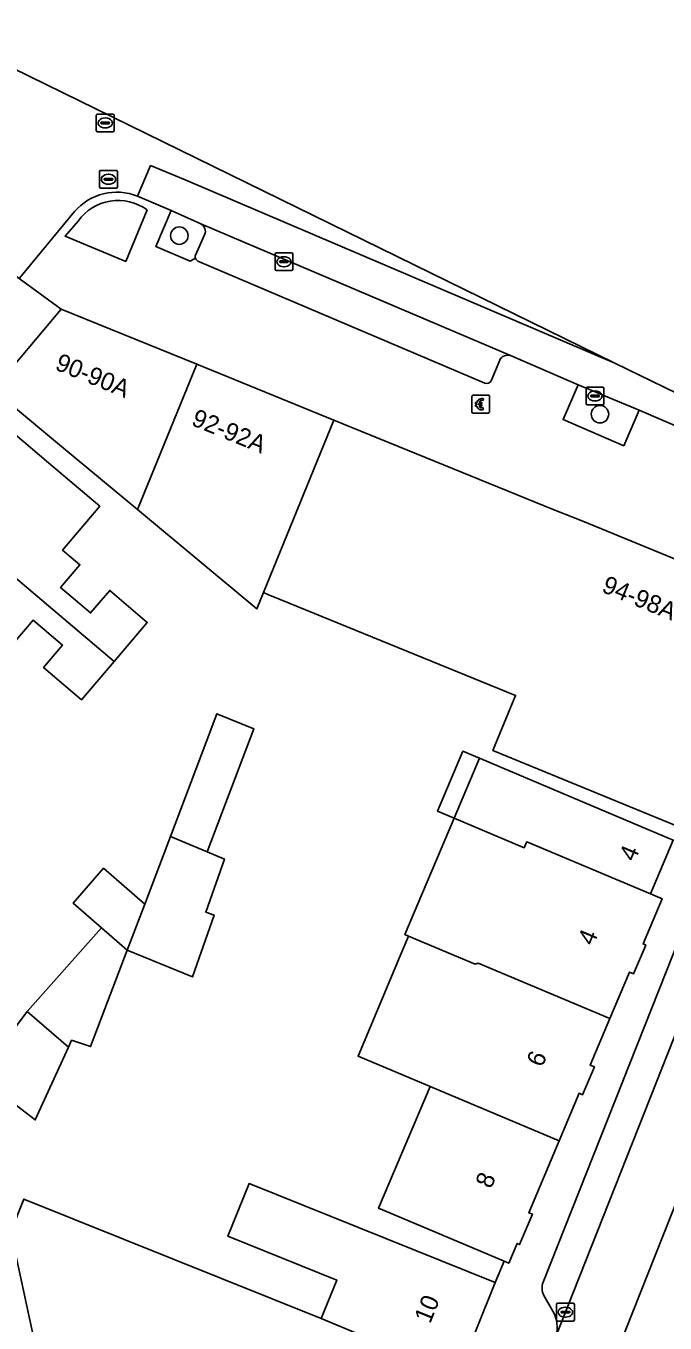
# Model space of a CAD drawing. Extents: x 161798 to 162385, y 382315 to 382833.
# Drawn here: x 162153.3 to 162189.2, y 382587 to 382659.8 of the extents above; entities that cross this region are included whole.
import ezdxf

# ---------------------------------------------------------------- set-up
doc = ezdxf.new("R2010")
doc.units = 0
for name, color, linetype in [('IMGEO_Betaalautomaat', 7, 'Continuous'), ('IMGEO_Boom', 7, 'Continuous'), ('IMGEO_Erf', 7, 'Continuous'), ('IMGEO_Groenvoorziening', 7, 'Continuous'), ('IMGEO_Kolk', 7, 'Continuous'), ('IMGEO_Pand', 7, 'Continuous'), ('IMGEO_Pand_nummerreeks', 7, 'Continuous'), ('IMGEO_Parkeervlak_open', 7, 'Continuous'), ('IMGEO_Rijbaan_lokaal_gesloten', 7, 'Continuous'), ('IMGEO_Rijbaan_lokaal_open', 7, 'Continuous'), ('IMGEO_Rioolput', 7, 'Continuous'), ('IMGEO_Voetpad_open', 7, 'Continuous')]:
    doc.layers.add(name, color=color, linetype=linetype)

msp = doc.modelspace()

# ---------------------------------------------------------------- linework, layer by layer
at = {"layer": 'IMGEO_Betaalautomaat'}
for p, q in [((162178.31, 382638.121), (162178.31, 382638.962)), ((162178.31, 382638.962), (162178.31, 382638.121)), ((162178.385, 382639.045), (162179.226, 382639.045)), ((162179.226, 382639.045), (162178.385, 382639.045)), ((162179.309, 382638.971), (162179.309, 382638.13)), ((162179.309, 382638.13), (162179.309, 382638.971)), ((162178.593, 382638.509), (162178.593, 382638.577)), ((162178.714, 382638.577), (162178.714, 382638.509)), ((162178.972, 382638.85), (162178.955, 382638.75)), ((162178.959, 382638.344), (162178.981, 382638.257)), ((162179.235, 382638.046), (162178.394, 382638.046)), ((162178.394, 382638.046), (162179.235, 382638.046))]:
    msp.add_line(p, q, dxfattribs=at)
for points in [[(162178.593, 382638.577), (162178.524, 382638.577), (162178.524, 382638.646), (162178.603, 382638.646)], [(162178.598, 382638.44), (162178.524, 382638.44), (162178.524, 382638.509), (162178.593, 382638.509)], [(162178.725, 382638.646), (162178.872, 382638.646), (162178.872, 382638.577), (162178.714, 382638.577)], [(162178.714, 382638.509), (162178.872, 382638.509), (162178.872, 382638.44), (162178.728, 382638.44)]]:
    msp.add_lwpolyline(points, dxfattribs=at)
for centre, radius, start, end in [((162178.388, 382638.968), 0.0779, 92.4484, 184.28452), ((162178.388, 382638.968), 0.0779, 92.4484, 184.28452), ((162179.232, 382638.968), 0.0779, 2.4484, 94.28452), ((162179.232, 382638.968), 0.0779, 2.4484, 94.28452), ((162178.859, 382638.495), 0.267, 191.80956, 297.03891), ((162178.886, 382638.57), 0.293, 73.01398, 165.01395), ((162178.892, 382638.583), 0.179, 69.32359, 159.56827), ((162178.892, 382638.51), 0.179, 202.76249, 291.86925), ((162178.388, 382638.124), 0.0779, 182.4484, 274.28452), ((162178.388, 382638.124), 0.0779, 182.4484, 274.28452), ((162179.232, 382638.124), 0.0779, 272.4484, 4.28452), ((162179.232, 382638.124), 0.0779, 272.4484, 4.28452)]:
    msp.add_arc(centre, radius, start, end, dxfattribs=at)
at = {"layer": 'IMGEO_Boom'}
for centre in [(162161.894, 382648.007), (162185.512, 382637.983)]:
    msp.add_circle(centre, 0.489, dxfattribs=at)
at = {"layer": 'IMGEO_Erf'}
for points in [[(162189.718, 382614.907), (162179.5, 382619.11), (162180.771, 382622.2), (162167.559, 382627.583), (162166.862, 382627.867), (162166.619, 382627.966), (162166.249, 382627.058), (162159.547, 382632.625), (162155.283, 382636.167), (162151.434, 382639.358)], [(162150.752, 382638.476), (162154.546, 382635.258), (162157.427, 382632.815), (162155.342, 382630.356), (162156.314, 382629.532), (162155.23, 382628.253), (162156.914, 382626.824), (162157.985, 382628.086), (162160.094, 382626.297), (162158.226, 382624.094), (162156.409, 382621.952), (162154.269, 382623.768), (162155.33, 382625.019), (162153.684, 382626.414), (162152.605, 382625.142)], [(162153.719, 382586.097), (162152.432, 382592.088), (162153.17, 382593.924), (162169.858, 382587.213), (162170.728, 382589.376), (162164.617, 382591.834), (162165.808, 382594.796), (162179.636, 382589.236), (162180.133, 382590.434), (162175.788, 382592.269), (162173.084, 382593.41), (162175.969, 382600.244), (162171.926, 382601.949), (162174.296, 382607.57), (162174.764, 382608.68), (162174.561, 382608.766), (162177.32, 382615.302), (162176.391, 382615.693), (162177.812, 382619.058), (162178.74, 382618.666), (162185.017, 382616.016), (162189.623, 382614.072)]]:
    msp.add_lwpolyline(points, dxfattribs=at)
msp.add_lwpolyline([(162153.357, 382604.46), (162157.522, 382609.158), (162155.937, 382610.533), (162157.637, 382612.493), (162159.954, 382610.482), (162161.391, 382614.281), (162163.398, 382619.568), (162164.006, 382621.171), (162166.079, 382620.322), (162163.458, 382613.415), (162164.421, 382613.012), (162163.386, 382610.027), (162163.843, 382609.869), (162162.639, 382606.397), (162158.97, 382607.901), (162156.913, 382602.479), (162155.839, 382602.843), (162155.664, 382602.458), (162153.802, 382598.368), (162150.609, 382600.809)], close=True, dxfattribs=at)
at = {"layer": 'IMGEO_Groenvoorziening'}
for points in [[(162156.208, 382648.82), (162155.475, 382647.977), (162158.88, 382646.556), (162160.087, 382649.446)], [(162163.099, 382648.663), (162161.431, 382649.415), (162160.58, 382647.389), (162162.505, 382646.576), (162162.801, 382646.737)], [(162162.794, 382646.916), (162163.309, 382648.058)]]:
    msp.add_lwpolyline(points, dxfattribs=at)
msp.add_lwpolyline([(162187.705, 382638.215), (162184.295, 382639.63), (162183.445, 382637.678), (162186.844, 382636.214)], close=True, dxfattribs=at)
for centre, radius, start, end in [((162158.455, 382647.225), 2.756, 53.70431, 144.6306), ((162162.905, 382648.257), 0.45, 333.83939, 64.44515), ((162163.087, 382646.838), 0.304, 165.08541, 199.39355)]:
    msp.add_arc(centre, radius, start, end, dxfattribs=at)
at = {"layer": 'IMGEO_Kolk'}
for p, q in [((162167.266, 382646.117), (162167.266, 382646.969)), ((162167.341, 382647.043), (162168.193, 382647.043)), ((162168.267, 382646.969), (162168.267, 382646.117)), ((162167.525, 382646.537), (162167.525, 382646.549)), ((162167.963, 382646.5), (162167.565, 382646.5)), ((162167.568, 382646.586), (162167.966, 382646.586)), ((162167.777, 382646.263), (162167.752, 382646.263)), ((162167.754, 382646.823), (162167.779, 382646.823)), ((162168.009, 382646.549), (162168.009, 382646.537)), ((162168.193, 382646.043), (162167.341, 382646.043)), ((162184.734, 382638.579), (162184.734, 382639.431)), ((162184.809, 382639.505), (162185.661, 382639.505)), ((162184.993, 382638.999), (162184.993, 382639.011)), ((162185.431, 382638.962), (162185.033, 382638.962)), ((162185.036, 382639.048), (162185.434, 382639.048)), ((162185.222, 382639.285), (162185.247, 382639.285)), ((162185.477, 382639.011), (162185.477, 382638.999)), ((162185.735, 382639.431), (162185.735, 382638.579)), ((162185.661, 382638.505), (162184.809, 382638.505)), ((162185.245, 382638.725), (162185.22, 382638.725)), ((162183.072, 382587.148), (162183.072, 382588)), ((162183.147, 382588.074), (162183.999, 382588.074)), ((162184.073, 382588), (162184.073, 382587.148)), ((162183.331, 382587.568), (162183.331, 382587.58)), ((162183.769, 382587.531), (162183.371, 382587.531)), ((162183.374, 382587.617), (162183.772, 382587.617)), ((162183.583, 382587.294), (162183.558, 382587.294)), ((162183.56, 382587.854), (162183.585, 382587.854)), ((162183.815, 382587.58), (162183.815, 382587.568)), ((162183.999, 382587.074), (162183.147, 382587.074))]:
    msp.add_line(p, q, dxfattribs=at)
for points in [[(162167.266, 382646.117), (162167.266, 382646.969)], [(162167.341, 382647.043), (162168.193, 382647.043)], [(162168.267, 382646.969), (162168.267, 382646.117)], [(162168.193, 382646.043), (162167.341, 382646.043)], [(162184.734, 382638.579), (162184.734, 382639.431)], [(162184.809, 382639.505), (162185.661, 382639.505)], [(162185.735, 382639.431), (162185.735, 382638.579)], [(162185.661, 382638.505), (162184.809, 382638.505)], [(162183.072, 382587.148), (162183.072, 382588)], [(162183.147, 382588.074), (162183.999, 382588.074)], [(162184.073, 382588), (162184.073, 382587.148)], [(162183.999, 382587.074), (162183.147, 382587.074)]]:
    msp.add_lwpolyline(points, dxfattribs=at)
for centre, radius, start, end in [((162167.343, 382646.967), 0.0765, 91.55205, 178.44795), ((162167.343, 382646.967), 0.0765, 91.55205, 178.44795), ((162168.191, 382646.967), 0.0765, 1.55205, 88.44795), ((162168.191, 382646.967), 0.0765, 1.55205, 88.44795), ((162167.565, 382646.546), 0.0403, 85.87752, 175.75265), ((162167.562, 382646.536), 0.0366, 178.93798, 274.71019), ((162167.966, 382646.543), 0.043, 264.86636, 352.45326), ((162167.97, 382646.548), 0.0386, 1.73085, 96.63898), ((162167.343, 382646.119), 0.0765, 181.55205, 268.44795), ((162167.343, 382646.119), 0.0765, 181.55205, 268.44795), ((162168.191, 382646.119), 0.0765, 271.55205, 358.44795), ((162168.191, 382646.119), 0.0765, 271.55205, 358.44795), ((162184.811, 382639.429), 0.0765, 91.55205, 178.44795), ((162184.811, 382639.429), 0.0765, 91.55205, 178.44795), ((162185.033, 382639.008), 0.0403, 85.87752, 175.75265), ((162185.03, 382638.998), 0.0366, 178.93798, 274.71019), ((162185.434, 382639.005), 0.043, 264.86636, 352.45326), ((162185.438, 382639.01), 0.0386, 1.73085, 96.63898), ((162185.659, 382639.429), 0.0765, 1.55205, 88.44795), ((162185.659, 382639.429), 0.0765, 1.55205, 88.44795), ((162184.811, 382638.581), 0.0765, 181.55205, 268.44795), ((162184.811, 382638.581), 0.0765, 181.55205, 268.44795), ((162185.659, 382638.581), 0.0765, 271.55205, 358.44795), ((162185.659, 382638.581), 0.0765, 271.55205, 358.44795), ((162183.149, 382587.998), 0.0765, 91.55205, 178.44795), ((162183.149, 382587.998), 0.0765, 91.55205, 178.44795), ((162183.997, 382587.998), 0.0765, 1.55205, 88.44795), ((162183.997, 382587.998), 0.0765, 1.55205, 88.44795), ((162183.371, 382587.577), 0.0403, 85.87752, 175.75265), ((162183.368, 382587.567), 0.0366, 178.93798, 274.71019), ((162183.772, 382587.574), 0.043, 264.86636, 352.45326), ((162183.776, 382587.579), 0.0386, 1.73085, 96.63898), ((162183.149, 382587.15), 0.0765, 181.55205, 268.44795), ((162183.149, 382587.15), 0.0765, 181.55205, 268.44795), ((162183.997, 382587.15), 0.0765, 271.55205, 358.44795), ((162183.997, 382587.15), 0.0765, 271.55205, 358.44795)]:
    msp.add_arc(centre, radius, start, end, dxfattribs=at)
for centre, major_axis, ratio, start_param, end_param in [((162167.753, 382646.543), (-0.387, 0.002), 0.722429, 4.712389, 7.853982), ((162167.778, 382646.543), (-0.39, 0.002), 0.717154, 1.570796, 4.712389), ((162185.221, 382639.005), (-0.387, 0.002), 0.722429, 4.712389, 7.853982), ((162185.246, 382639.005), (-0.39, 0.002), 0.717154, 1.570796, 4.712389), ((162183.559, 382587.574), (-0.387, 0.002), 0.722429, 4.712389, 7.853982), ((162183.584, 382587.574), (-0.39, 0.002), 0.717154, 1.570796, 4.712389)]:
    msp.add_ellipse(centre, major_axis=major_axis, ratio=ratio, start_param=start_param, end_param=end_param, dxfattribs=at)
at = {"layer": 'IMGEO_Pand'}
for points in [[(162159.547, 382632.625), (162162.871, 382640.784), (162155.256, 382643.887), (162151.434, 382639.358), (162155.283, 382636.167)], [(162170.563, 382637.65), (162162.871, 382640.784), (162159.547, 382632.625), (162166.249, 382627.058), (162166.619, 382627.966)], [(162146.784, 382633.798), (162158.226, 382624.094), (162160.094, 382626.297), (162157.985, 382628.086), (162156.914, 382626.824), (162155.23, 382628.253), (162156.314, 382629.532), (162155.342, 382630.356), (162157.427, 382632.815), (162154.546, 382635.258), (162150.752, 382638.476)], [(162170.563, 382637.65), (162166.619, 382627.966), (162166.862, 382627.867), (162167.559, 382627.583), (162180.771, 382622.2), (162179.5, 382619.11), (162189.718, 382614.907), (162194.979, 382627.699), (162184.555, 382631.986), (162182.876, 382632.633)], [(162146.784, 382633.798), (162142.914, 382629.235), (162149.395, 382623.739), (162149.537, 382623.616), (162149.656, 382623.757), (162151.574, 382626.017), (162152.605, 382625.142), (162153.684, 382626.414), (162155.33, 382625.019), (162154.269, 382623.768), (162156.409, 382621.952), (162158.226, 382624.094)], [(162161.391, 382614.281), (162163.458, 382613.415), (162166.079, 382620.322), (162164.006, 382621.171), (162163.398, 382619.568)], [(162178.74, 382618.666), (162177.812, 382619.058), (162176.391, 382615.693), (162177.32, 382615.302)], [(162185.017, 382616.016), (162178.74, 382618.666), (162177.32, 382615.302), (162181.254, 382613.646), (162181.397, 382613.986), (162188.352, 382611.061), (162189.623, 382614.072)], [(162186.072, 382604.052), (162187.175, 382606.665), (162187.401, 382606.57), (162188.08, 382608.179), (162187.93, 382608.243), (162189.004, 382610.786), (162188.352, 382611.061), (162181.397, 382613.986), (162181.254, 382613.646), (162177.32, 382615.302), (162174.561, 382608.766), (162174.764, 382608.68), (162178.504, 382607.113), (162178.67, 382607.167)], [(162164.421, 382613.012), (162163.458, 382613.415), (162161.391, 382614.281), (162159.954, 382610.482), (162158.97, 382607.901), (162162.639, 382606.397), (162163.843, 382609.869), (162163.386, 382610.027)], [(162159.954, 382610.482), (162157.637, 382612.493), (162155.937, 382610.533), (162157.522, 382609.158), (162158.97, 382607.901)], [(162158.97, 382607.901), (162157.522, 382609.158), (162153.357, 382604.46), (162155.664, 382602.458), (162155.839, 382602.843), (162156.913, 382602.479)], [(162175.969, 382600.244), (162183.215, 382597.194), (162184.341, 382599.861), (162184.536, 382599.778), (162185.196, 382601.342), (162184.969, 382601.438), (162186.072, 382604.052), (162178.67, 382607.167), (162178.504, 382607.113), (162174.764, 382608.68), (162174.296, 382607.57), (162171.926, 382601.949)], [(162150.609, 382600.809), (162153.802, 382598.368), (162155.664, 382602.458), (162153.357, 382604.46)], [(162175.969, 382600.244), (162173.084, 382593.41), (162175.788, 382592.269), (162180.133, 382590.434), (162180.394, 382590.324), (162180.861, 382591.431), (162181.001, 382591.372), (162181.717, 382593.068), (162181.511, 382593.155), (162183.215, 382597.194)], [(162169.858, 382587.213), (162177.539, 382584.02), (162179.636, 382589.236), (162165.808, 382594.796), (162164.617, 382591.834), (162170.728, 382589.376)], [(162169.858, 382587.213), (162153.17, 382593.924), (162152.432, 382592.088), (162153.719, 382586.097), (162163.057, 382582.342), (162175.121, 382577.623), (162177.487, 382583.507), (162177.354, 382583.56), (162177.539, 382584.02)]]:
    msp.add_lwpolyline(points, close=True, dxfattribs=at)
at = {"layer": 'IMGEO_Parkeervlak_open'}
for points in [[(162180.495, 382641.275), (162163.099, 382648.663)], [(162163.309, 382648.058), (162162.794, 382646.916)], [(162162.939, 382646.578), (162179.042, 382639.731)], [(162179.409, 382639.864), (162179.883, 382641.024)], [(162195.498, 382622.698), (162194.908, 382621.019), (162191.828, 382613.249), (162190.44, 382609.748), (162182.318, 382589.26)], [(162183.036, 382586.209), (162196.606, 382620.511)], [(162182.369, 382588.517), (162182.871, 382587.63)]]:
    msp.add_lwpolyline(points, dxfattribs=at)
for centre, radius, start, end in [((162162.905, 382648.257), 0.45, 333.83939, 64.44515), ((162163.087, 382646.838), 0.304, 165.08541, 199.39355), ((162163.077, 382646.837), 0.294, 199.94313, 241.9679), ((162180.341, 382640.78), 0.519, 72.68789, 151.91219), ((162179.15, 382640.006), 0.296, 248.62391, 331.2169), ((162183.118, 382588.942), 0.861, 158.30413, 209.54919), ((162181.266, 382586.724), 1.843, 343.78925, 29.45727)]:
    msp.add_arc(centre, radius, start, end, dxfattribs=at)
at = {"layer": 'IMGEO_Rijbaan_lokaal_gesloten'}
msp.add_lwpolyline([(162186.349, 382640.853), (162162.23, 382651.135), (162160.282, 382651.935), (162159.545, 382650.218), (162161.431, 382649.415), (162163.099, 382648.663), (162180.495, 382641.275), (162184.295, 382639.63), (162187.705, 382638.215), (162190.539, 382636.999), (162191.188, 382638.482)], close=True, dxfattribs=at)
at = {"layer": 'IMGEO_Rijbaan_lokaal_open'}
for points in [[(162186.349, 382640.853), (162141.217, 382662.958), (162149.174, 382657.964), (162148.157, 382656.334)], [(162159.545, 382650.218), (162160.282, 382651.935), (162162.23, 382651.135), (162186.349, 382640.853)], [(162150.085, 382647.684), (162152.892, 382645.592), (162152.916, 382645.619), (162156.011, 382649.355)]]:
    msp.add_lwpolyline(points, dxfattribs=at)
msp.add_lwpolyline([(162193.938, 382604.183), (162196.082, 382609.705), (162197.87, 382614.249), (162197.933, 382614.428), (162200.724, 382621.462), (162201.9, 382624.403), (162198.611, 382625.691), (162198.183, 382624.669), (162196.606, 382620.511), (162183.036, 382586.209), (162181.51, 382582.342), (162184.773, 382581.075), (162192.527, 382600.624)], close=True, dxfattribs=at)
msp.add_arc((162158.376, 382647.338), 3.108, 67.90152, 139.5445, dxfattribs=at)
at = {"layer": 'IMGEO_Rioolput'}
for p, q in [((162157.232, 382653.908), (162157.232, 382654.76)), ((162157.307, 382654.834), (162158.159, 382654.834)), ((162157.491, 382654.328), (162157.491, 382654.34)), ((162157.929, 382654.291), (162157.531, 382654.291)), ((162157.534, 382654.377), (162157.932, 382654.377)), ((162157.72, 382654.614), (162157.745, 382654.614)), ((162157.975, 382654.34), (162157.975, 382654.328)), ((162158.233, 382654.76), (162158.233, 382653.908)), ((162158.159, 382653.834), (162157.307, 382653.834)), ((162157.743, 382654.054), (162157.718, 382654.054)), ((162157.415, 382650.745), (162157.415, 382651.597)), ((162157.49, 382651.671), (162158.342, 382651.671)), ((162157.903, 382651.451), (162157.928, 382651.451)), ((162158.416, 382651.597), (162158.416, 382650.745)), ((162158.342, 382650.671), (162157.49, 382650.671)), ((162157.674, 382651.165), (162157.674, 382651.177)), ((162158.112, 382651.128), (162157.714, 382651.128)), ((162157.717, 382651.214), (162158.115, 382651.214)), ((162157.926, 382650.891), (162157.901, 382650.891)), ((162158.158, 382651.177), (162158.158, 382651.165))]:
    msp.add_line(p, q, dxfattribs=at)
for points in [[(162157.232, 382653.908), (162157.232, 382654.76)], [(162157.307, 382654.834), (162158.159, 382654.834)], [(162158.233, 382654.76), (162158.233, 382653.908)], [(162158.159, 382653.834), (162157.307, 382653.834)], [(162157.415, 382650.745), (162157.415, 382651.597)], [(162157.49, 382651.671), (162158.342, 382651.671)], [(162158.416, 382651.597), (162158.416, 382650.745)], [(162158.342, 382650.671), (162157.49, 382650.671)]]:
    msp.add_lwpolyline(points, dxfattribs=at)
for centre, radius, start, end in [((162157.309, 382654.758), 0.0765, 91.55205, 178.44795), ((162157.309, 382654.758), 0.0765, 91.55205, 178.44795), ((162157.531, 382654.337), 0.0403, 85.87752, 175.75265), ((162157.528, 382654.327), 0.0366, 178.93798, 274.71019), ((162157.932, 382654.334), 0.043, 264.86636, 352.45326), ((162157.936, 382654.339), 0.0386, 1.73085, 96.63898), ((162158.157, 382654.758), 0.0765, 1.55205, 88.44795), ((162158.157, 382654.758), 0.0765, 1.55205, 88.44795), ((162157.309, 382653.91), 0.0765, 181.55205, 268.44795), ((162157.309, 382653.91), 0.0765, 181.55205, 268.44795), ((162158.157, 382653.91), 0.0765, 271.55205, 358.44795), ((162158.157, 382653.91), 0.0765, 271.55205, 358.44795), ((162157.492, 382651.595), 0.0765, 91.55205, 178.44795), ((162157.492, 382651.595), 0.0765, 91.55205, 178.44795), ((162158.34, 382651.595), 0.0765, 1.55205, 88.44795), ((162158.34, 382651.595), 0.0765, 1.55205, 88.44795), ((162157.492, 382650.747), 0.0765, 181.55205, 268.44795), ((162157.492, 382650.747), 0.0765, 181.55205, 268.44795), ((162157.714, 382651.174), 0.0403, 85.87752, 175.75265), ((162157.711, 382651.164), 0.0366, 178.93798, 274.71019), ((162158.115, 382651.171), 0.043, 264.86636, 352.45326), ((162158.119, 382651.176), 0.0386, 1.73085, 96.63898), ((162158.34, 382650.747), 0.0765, 271.55205, 358.44795), ((162158.34, 382650.747), 0.0765, 271.55205, 358.44795)]:
    msp.add_arc(centre, radius, start, end, dxfattribs=at)
for centre, major_axis, ratio, start_param, end_param in [((162157.719, 382654.334), (-0.387, 0.002), 0.722429, 4.712389, 7.853982), ((162157.744, 382654.334), (-0.39, 0.002), 0.717154, 1.570796, 4.712389), ((162157.902, 382651.171), (-0.387, 0.002), 0.722429, 4.712389, 7.853982), ((162157.927, 382651.171), (-0.39, 0.002), 0.717154, 1.570796, 4.712389)]:
    msp.add_ellipse(centre, major_axis=major_axis, ratio=ratio, start_param=start_param, end_param=end_param, dxfattribs=at)
at = {"layer": 'IMGEO_Voetpad_open'}
for points in [[(162162.801, 382646.737), (162162.505, 382646.576), (162160.58, 382647.389), (162161.431, 382649.415), (162159.545, 382650.218)], [(162156.011, 382649.355), (162152.916, 382645.619), (162152.892, 382645.592), (162155.256, 382643.887), (162162.871, 382640.784), (162170.563, 382637.65), (162182.876, 382632.633), (162184.555, 382631.986), (162194.979, 382627.699), (162198.772, 382626.104), (162200.244, 382629.872)], [(162160.087, 382649.446), (162158.88, 382646.556), (162155.475, 382647.977), (162156.208, 382648.82)], [(162179.042, 382639.731), (162162.939, 382646.578)], [(162088.523, 382582.702), (162089.165, 382581.708), (162091.498, 382583.245), (162093.517, 382584.575), (162100.557, 382589.214), (162099.697, 382590.512), (162104.937, 382593.957), (162104.785, 382594.155), (162112.146, 382598.926), (162116.822, 382602.004), (162119.59, 382603.578), (162123.441, 382606.277), (162123.564, 382606.422), (162127.433, 382610.984), (162131.303, 382615.547), (162135.174, 382620.109), (162139.044, 382624.672), (162142.914, 382629.235), (162146.784, 382633.798), (162150.752, 382638.476), (162151.434, 382639.358), (162155.256, 382643.887), (162152.892, 382645.592)], [(162198.797, 382633.462), (162190.539, 382636.999), (162187.705, 382638.215), (162186.844, 382636.214), (162183.445, 382637.678), (162184.295, 382639.63), (162180.495, 382641.275)], [(162179.883, 382641.024), (162179.409, 382639.864)], [(162182.318, 382589.26), (162190.44, 382609.748), (162191.828, 382613.249), (162194.908, 382621.019), (162195.498, 382622.698)], [(162197.87, 382614.249), (162196.082, 382609.705), (162193.938, 382604.183), (162192.527, 382600.624), (162184.773, 382581.075), (162182.222, 382574.642), (162181.625, 382573.137)], [(162189.623, 382614.072), (162188.352, 382611.061), (162189.004, 382610.786), (162187.93, 382608.243), (162188.08, 382608.179), (162187.401, 382606.57), (162187.175, 382606.665), (162186.072, 382604.052), (162184.969, 382601.438), (162185.196, 382601.342), (162184.536, 382599.778), (162184.341, 382599.861), (162183.215, 382597.194), (162181.511, 382593.155), (162181.717, 382593.068), (162181.001, 382591.372), (162180.861, 382591.431), (162180.394, 382590.324), (162180.133, 382590.434), (162179.636, 382589.236), (162177.539, 382584.02)], [(162182.871, 382587.63), (162182.369, 382588.517)]]:
    msp.add_lwpolyline(points, dxfattribs=at)
for centre, radius, start, end in [((162158.376, 382647.338), 3.108, 67.90152, 139.5445), ((162158.455, 382647.225), 2.756, 53.70431, 144.6306), ((162163.077, 382646.837), 0.294, 199.94313, 241.9679), ((162180.341, 382640.78), 0.519, 72.68789, 151.91219), ((162179.15, 382640.006), 0.296, 248.62391, 331.2169), ((162183.118, 382588.942), 0.861, 158.30413, 209.54919), ((162181.266, 382586.724), 1.843, 343.78925, 29.45727)]:
    msp.add_arc(centre, radius, start, end, dxfattribs=at)

# ---------------------------------------------------------------- texts
at = {"layer": 'IMGEO_Pand_nummerreeks'}
for s, rotation, p in [('90-90A', 337.83115, (162154.856, 382640.508)), ('92-92A', 337.83226, (162162.51, 382637.389)), ('94-98A', 337.64319, (162185.553, 382628.028)), ('4', 67.11628, (162187.465, 382612.816)), ('4', 67.17961, (162185.139, 382608.099)), ('6', 67.17961, (162182.269, 382601.279)), ('8', 67.17961, (162179.401, 382594.461)), ('10', 68.09828, (162175.977, 382586.889))]:
    msp.add_text(s, height=1, rotation=rotation, dxfattribs=at).set_placement(p)

doc.saveas('drawing.dxf')
